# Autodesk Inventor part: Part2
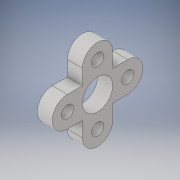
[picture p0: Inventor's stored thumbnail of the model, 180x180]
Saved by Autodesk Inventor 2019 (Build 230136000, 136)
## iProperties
Created: 2019-07
Part Number: Part2
Material: Generic
Document SubType Name: Modeling
Designer: Synergysoft
Density: 1 g/cm^3
Appearance: Default
Author: Synergysoft
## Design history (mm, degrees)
sketch "Sketch1"
  geometry: L1 (0, 100)-(0, -100); L2 (-50, 100)-(-50, -100); L3 (50, -100)-(50, 100); L4 (100, 0)-(-100, 0); L5 (100, 50)-(-100, 50); L6 (-100, -50)-(100, -50); C1 r 20 at (100, 0); C2 r 20 at (0, 100); C3 r 20 at (-100, 0); C4 r 20 at (0, -100); A1 r 50 centre (0, 100) between (50, 100) and (-50, 100); A2 r 50 centre (0, -100) between (-50, -100) and (50, -100); A3 r 50 centre (100, 0) between (100, -50) and (100, 50); A4 r 50 centre (-100, 0) between (-100, 50) and (-100, -50); 3 further points
  constraints: 16 end point, 8 centre point, 8 point on circle, 8 tangent, 3 coincident, 2 midpoint, 2 parallel, 1 horizontal, 1 vertical, 9 other
  dimensions: "d0" = 200 distance of L1.start L1.end; "d1" = 50 radius of A2; "d2" = 100 diameter of A4; "d3" = 200 distance of L4.start L4.end; "d4" = 40 diameter of C1; "d7" = 360 deg dimension on point (0, 0) C1.centre (derived)
extrude "Extrusion1" new body sketch "Sketch1" distance "d10" = 50; taper "d11" = 0 deg
sketch "Sketch2"
  geometry: L1 (-50, -50)-(-50, -100) reference; L2 (-100, -50)-(-50, -50) reference; 2 further points
  dimensions: "d12" = 50 distance from line of L1 point (0, 0); "d13" = 50 distance from line of L2 point (0, 0)
hole "Hole1" sketch "Sketch2" at (0, 0) diameter "d14" = 100; stored, may be unused: countersink angle "d18" = 90 deg, drill point angle "d20" = 118 deg; dims "d15" = 6, "d16" = 4, "d17" = 2, "d19" = 8
body "Solid1"
